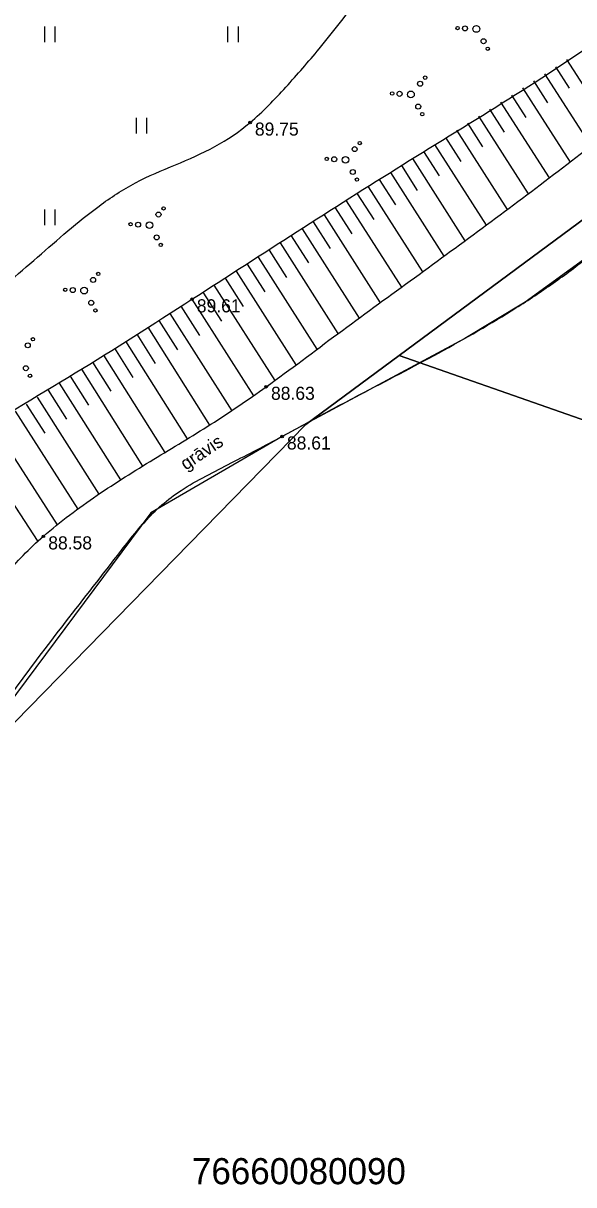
# Model space of a CAD drawing. Extents: x 635228 to 635525, y 248590 to 248800.
# Drawn here: x 635410.17 to 635431.23, y 248638.32 to 248682.72 of the extents above; entities that cross this region are included whole.
import ezdxf

# ---------------------------------------------------------------- set-up
doc = ezdxf.new("R2010")
doc.units = 0
for name, color, linetype in [('HIDG_GRAV_####_####_#', 7, 'Continuous'), ('HIDG_GRAV_####_TKST_#', 7, 'Continuous'), ('RAMI_UZMR_####_####_#', 7, 'Continuous'), ('RELJ_AATZ_####_TKST_#', 7, 'Continuous'), ('RELJ_ELEM_####_####_#', 7, 'Continuous'), ('RELJ_HORZ_RESN_####_#', 7, 'Continuous'), ('RELJ_NOGA_####_####_#', 7, 'Continuous'), ('ROBZ_IERR_####_####_#', 7, 'Continuous'), ('ROBZ_UZMR_####_####_#', 7, 'Continuous'), ('ROBZ_UZMR_####_TKST_#', 7, 'Continuous'), ('TERT_ELEM_####_####_#', 7, 'Continuous'), ('TERT_KONT_####_####_#', 7, 'Continuous')]:
    doc.layers.add(name, color=color, linetype=linetype)

msp = doc.modelspace()

# ---------------------------------------------------------------- linework, layer by layer
at = {"layer": 'HIDG_GRAV_####_####_#'}
for points in [[(635394.244, 248623.295), (635394.9074355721, 248630.6631552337), (635396.5650242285, 248636.944974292), (635397.8888882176, 248639.97580624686), (635399.2686043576, 248642.98780740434), (635400.0423829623, 248644.69884236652), (635400.835233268, 248646.3905777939), (635402.4795660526, 248649.72803076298), (635404.20443685, 248653.0239277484), (635406.0126797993, 248656.30203018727), (635407.0670223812, 248658.14081276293), (635408.1930324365, 248659.92698593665), (635409.4621962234, 248661.60192368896), (635410.172800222, 248662.37935865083), (635410.946, 248663.10700000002), (635413.0008032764, 248664.6744257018), (635415.1640977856, 248666.05372522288), (635417.3478434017, 248667.38916213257), (635419.464, 248668.825), (635422.2083511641, 248670.85354035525), (635424.965867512, 248672.86854694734), (635430.4558647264, 248676.93578902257), (635435.8049295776, 248681.1823865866), (635438.3862804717, 248683.4215875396), (635439.6466024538, 248684.57867623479), (635440.8840000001, 248685.76400000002), (635443.6087249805, 248688.6747140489), (635446.1599310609, 248691.73220612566), (635448.6719216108, 248694.81834513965), (635451.279, 248697.815), (635453.9336502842, 248700.48189136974), (635456.6811388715, 248703.07136968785), (635459.3523080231, 248705.7266631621), (635461.7780000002, 248708.59100000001), (635461.778, 248708.59100000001)], [(635396.7397638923, 248625.2320466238), (635397.9986579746, 248634.27312358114), (635398.9188026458, 248636.96227546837), (635399.5920874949, 248638.24717771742), (635399.9292604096, 248638.88899780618), (635400.2466831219, 248639.53584001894), (635401.591165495, 248642.41958219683), (635402.9524948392, 248645.2868638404), (635405.8217854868, 248650.96088254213), (635407.5583128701, 248653.91205967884), (635409.4799859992, 248656.7354955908), (635411.5283407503, 248659.48290512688), (635413.6449129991, 248662.20600313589), (635414.8182615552, 248663.6538935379), (635415.4704678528, 248664.3057478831), (635416.2076616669, 248664.85985159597), (635417.1601741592, 248665.41138033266), (635418.1313630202, 248665.91742947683), (635419.1067857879, 248666.41122678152), (635420.072, 248666.926), (635421.5645353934, 248667.7418115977), (635423.0692260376, 248668.5354410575), (635426.0762392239, 248670.12612318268), (635429.0153718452, 248671.8379856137), (635430.4352117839, 248672.78309045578), (635431.128452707, 248673.2855892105), (635431.8089561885, 248673.81096758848), (635433.1953696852, 248675.0040709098), (635434.526751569, 248676.2563297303), (635437.0226234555, 248678.92292892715), (635441.762, 248684.467), (635443.1273679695, 248686.0473501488), (635444.4678763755, 248687.6485508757), (635447.1219662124, 248690.87245996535), (635449.819572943, 248694.05663907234), (635451.2144774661, 248695.60817732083), (635452.6560000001, 248697.119), (635458.0231966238, 248702.2419696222), (635463.584, 248707.15000000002)]]:
    msp.add_spline(points, degree=3, dxfattribs=at)
at = {"layer": 'RAMI_UZMR_####_####_#'}
msp.add_lwpolyline([(635426.003, 248728.15499999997), (635436.69, 248722.584), (635450.108, 248715.45700000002), (635458.287, 248711.34600000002), (635461.7780000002, 248708.59100000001), (635463.584, 248707.15000000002), (635452.6560000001, 248697.119), (635441.762, 248684.467), (635435.9528772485, 248677.73413872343), (635432.018527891, 248673.97985762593), (635429.363741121, 248672.06248825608), (635427.0556775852, 248670.66460585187), (635420.072, 248666.926), (635415.05332695, 248664.00973325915), (635408.095218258, 248654.65947737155), (635398.6701763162, 248636.43948679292), (635398.046283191, 248634.41686083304), (635396.3166782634, 248622.87374513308), (635394.244, 248623.295), (635390.206, 248622.483), (635381.566, 248626.41900000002), (635379.918, 248627.738), (635364.657, 248634.36500000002)], dxfattribs=at)
at = {"layer": 'RELJ_ELEM_####_####_#'}
for centre in [(635418.848, 248678.924), (635416.627, 248672.168), (635419.464, 248668.825), (635420.072, 248666.926), (635410.946, 248663.10700000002)]:
    msp.add_circle(centre, 0.05, dxfattribs=at)
at = {"layer": 'RELJ_HORZ_RESN_####_#'}
msp.add_spline([(635396.8403365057, 248673.83023932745), (635398.5699520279, 248674.74721849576), (635400.1196081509, 248675.6687893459), (635401.3847631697, 248676.59316814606), (635401.8779834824, 248677.05585311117), (635402.2608753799, 248677.51857116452), (635402.5005008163, 248677.92779942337), (635402.9962003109, 248679.47940420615), (635403.1093939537, 248680.10527297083), (635403.2077718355, 248680.73304831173), (635403.3050539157, 248681.36081107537), (635403.4149601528, 248681.98664210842), (635403.9947087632, 248684.49620174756), (635404.4941894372, 248685.58182624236), (635404.822447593, 248686.0525951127), (635405.213, 248686.464), (635405.5227683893, 248686.49325254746), (635405.8948771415, 248686.27621660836), (635406.269797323, 248686.04907236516), (635406.588, 248686.048), (635407.1331532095, 248686.47133617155), (635407.6549224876, 248686.94769115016), (635408.6437981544, 248688.02779111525), (635410.511320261, 248690.47588617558), (635412.43838879, 248692.8856225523), (635414.0718482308, 248694.36296271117), (635414.672826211, 248694.7503376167), (635415.8418707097, 248695.38166460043), (635417.0157559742, 248695.99905223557), (635418.2014500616, 248696.5900310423), (635419.4059210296, 248697.14213154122), (635424.3998390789, 248699.29274669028), (635429.4588912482, 248701.50672660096), (635434.3873884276, 248704.0886148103), (635435.2434356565, 248704.60530447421), (635437.7315604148, 248706.27775516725), (635439.1970704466, 248707.5552960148), (635439.8338858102, 248708.26101524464), (635440.1227716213, 248708.63326282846), (635440.3898668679, 248709.01944554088), (635440.6922176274, 248709.6864690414), (635440.8034457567, 248710.32396866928)], degree=3, dxfattribs=at)
at = {"layer": 'RELJ_NOGA_####_####_#'}
for p, q in [((635430.5266066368, 248681.05692283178), (635431.0519157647, 248680.24090699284)), ((635430.9470252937, 248681.3275667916), (635432.6731329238, 248678.64622909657)), ((635430.1061815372, 248680.7862888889), (635431.879304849, 248678.02717532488)), ((635429.2649208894, 248680.2456591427), (635431.084098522, 248677.41488158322)), ((635429.6855512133, 248680.5159740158), (635430.2245122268, 248679.67731004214)), ((635428.423315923, 248679.70556556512), (635430.2842333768, 248676.80569698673)), ((635428.8441217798, 248679.97560710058), (635429.3959754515, 248679.1156532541)), ((635428.0024688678, 248679.43558828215), (635428.5663567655, 248678.5554283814)), ((635427.1604519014, 248678.89613723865), (635427.7363538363, 248677.9972248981)), ((635427.5814603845, 248679.16586276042), (635429.4813910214, 248676.200303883)), ((635426.3183540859, 248678.35681247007), (635426.9051811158, 248677.43969685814)), ((635426.7394434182, 248678.62641171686), (635428.6783507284, 248675.6000150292)), ((635425.8971919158, 248678.08732698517), (635427.8717630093, 248675.0013921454)), ((635425.0547269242, 248677.54857591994), (635427.0641464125, 248674.40564282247)), ((635425.4759878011, 248677.81790707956), (635426.0734693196, 248676.88338621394)), ((635424.6334638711, 248677.2792481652), (635425.2412367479, 248676.32791820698)), ((635423.7907590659, 248676.74087226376), (635424.408884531, 248675.77333768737)), ((635424.2121114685, 248677.0100602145), (635426.2553767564, 248673.8117939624)), ((635422.9479559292, 248676.20265032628), (635423.5759655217, 248675.21902551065)), ((635423.369385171, 248676.4717179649), (635425.4459030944, 248673.21935592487)), ((635422.5265266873, 248675.93358268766), (635424.6367393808, 248672.628445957)), ((635421.683602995, 248675.395549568), (635423.8268924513, 248672.03703705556)), ((635422.1050892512, 248675.6645278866), (635422.7430063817, 248674.66491831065)), ((635420.8406304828, 248674.8575929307), (635423.0178154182, 248671.4459665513)), ((635421.262116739, 248675.12657124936), (635421.9101732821, 248674.11107331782)), ((635420.4191442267, 248674.58861461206), (635421.0774288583, 248673.55708937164)), ((635419.5761717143, 248674.05065797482), (635420.2449094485, 248673.00275282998)), ((635419.9976579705, 248674.31963629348), (635422.2092448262, 248670.8541024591)), ((635418.7331992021, 248673.51270133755), (635419.4126894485, 248672.44794711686)), ((635419.1546854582, 248673.78167965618), (635421.4015228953, 248670.26090852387)), ((635418.311757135, 248673.2436537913), (635420.5957499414, 248669.66631951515)), ((635417.4688977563, 248672.70551991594), (635419.7908028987, 248669.0688049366)), ((635417.8903274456, 248672.9745868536), (635418.5811471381, 248671.89258127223)), ((635416.6260381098, 248672.1673864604), (635418.9818020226, 248668.47408559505)), ((635417.047468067, 248672.4364529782), (635417.7498791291, 248671.336292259)), ((635416.2043934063, 248671.89865673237), (635416.9130730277, 248670.7846281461)), ((635415.3598923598, 248671.36310347), (635416.0682259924, 248670.24203794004)), ((635415.7822665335, 248671.63068518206), (635418.1455230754, 248667.90264789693)), ((635414.5141425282, 248670.8295240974), (635415.2195002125, 248669.7073233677)), ((635414.9371250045, 248671.09614334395), (635417.2947611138, 248667.35588774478)), ((635414.0908198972, 248670.5634452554), (635416.4389943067, 248666.82757749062)), ((635413.2441746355, 248670.03128757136), (635415.5840345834, 248666.30864783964)), ((635413.6674972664, 248670.29736641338), (635414.3707254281, 248669.1785536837)), ((635412.3975310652, 248669.49912719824), (635414.7326200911, 248665.78930868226)), ((635412.8208520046, 248669.76520872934), (635413.521585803, 248668.65036444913)), ((635411.9743774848, 248669.23277959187), (635412.674411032, 248668.12061753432)), ((635411.1286100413, 248668.69922813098), (635411.8312024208, 248667.58616171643)), ((635411.5514225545, 248668.96611683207), (635413.8901244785, 248665.2610801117)), ((635410.2841650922, 248668.1635865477), (635410.9965072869, 248667.04570592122)), ((635410.7061891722, 248668.43172009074), (635413.0645891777, 248664.71781451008)), ((635409.8625812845, 248667.8947613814), (635412.2588250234, 248664.15017364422)), ((635409.0209685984, 248667.3546810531), (635411.471024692, 248663.54545166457)), ((635408.1819740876, 248666.81054345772), (635410.7270639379, 248662.91267369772))]:
    msp.add_line(p, q, dxfattribs=at)
msp.add_spline([(635390.206, 248622.483), (635392.6761559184, 248639.41621940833), (635395.6724652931, 248647.2597307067), (635397.9131924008, 248650.95381667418), (635399.048256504, 248652.79837067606), (635400.128, 248654.662), (635400.9493075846, 248656.2558432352), (635403.3016292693, 248661.16811378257), (635405.1862207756, 248664.14373210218), (635407.706, 248666.499), (635412.1610828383, 248669.3503906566), (635416.627, 248672.168), (635424.6828055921, 248677.31078055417), (635432.728, 248682.47600000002), (635436.7060689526, 248685.70428438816), (635438.5008534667, 248687.5575466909), (635440.2150000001, 248689.48700000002), (635442.5291182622, 248692.3528262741), (635444.7219287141, 248695.30565037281), (635446.9190248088, 248698.24939928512), (635449.246, 248701.08800000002), (635451.3600052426, 248703.48451832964), (635453.4937434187, 248705.86484004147), (635457.9500000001, 248710.44), (635458.6576193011, 248711.10744185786)], degree=3, dxfattribs=at)
at = {"layer": 'ROBZ_IERR_####_####_#'}
msp.add_lwpolyline([(635522.337313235, 248635.85405923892), (635430.9589999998, 248667.77300000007), (635424.5429999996, 248670.01400000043), (635439.4570000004, 248681.03800000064), (635465.4589999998, 248707.53900000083), (635482.5609999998, 248729.82799999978), (635498.1289999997, 248747.85500000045)], dxfattribs=at)
at = {"layer": 'ROBZ_UZMR_####_####_#'}
msp.add_lwpolyline([(635325.5420000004, 248659.74000000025), (635329.6529999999, 248676.3660000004), (635327.79, 248676.82799999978), (635337.4600999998, 248688.65990000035), (635343.3430000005, 248703.1199999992), (635360.483, 248762.61500000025), (635458.6069999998, 248711.13399999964), (635465.4589999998, 248707.53900000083), (635439.4570000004, 248681.03800000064), (635424.5429999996, 248670.01400000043), (635420.9790000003, 248667.37900000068), (635407.0700000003, 248653.17999999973), (635400.0669999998, 248641.1490000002), (635395.1619999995, 248617.53900000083), (635389.0310000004, 248621.06200000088), (635375.858, 248629.11500000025)], close=True, dxfattribs=at)
msp.add_lwpolyline([(635432.3373132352, 248596.18186087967), (635395.1619999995, 248617.53900000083), (635400.0669999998, 248641.1490000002), (635407.0700000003, 248653.17999999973), (635420.9790000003, 248667.37900000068), (635424.5429999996, 248670.01400000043), (635430.9589999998, 248667.77300000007), (635522.3373132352, 248635.85405923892)], dxfattribs=at)
at = {"layer": 'TERT_ELEM_####_####_#'}
for p, q in [((635411, 248682), (635411, 248682.6)), ((635411.4, 248682), (635411.4, 248682.6)), ((635418, 248682), (635418, 248682.6)), ((635418.4, 248682), (635418.4, 248682.6)), ((635414.5, 248678.5), (635414.5, 248679.1)), ((635414.9, 248678.5), (635414.9, 248679.1)), ((635411, 248675), (635411, 248675.6)), ((635411.4, 248675), (635411.4, 248675.6))]:
    msp.add_line(p, q, dxfattribs=at)
for centre, radius in [((635426.7816, 248682.53423999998), 0.06400000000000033), ((635427.06608, 248682.52079999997), 0.09600000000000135), ((635427.5, 248682.5), 0.12800000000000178), ((635427.77648, 248682.03311999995), 0.09600000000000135), ((635427.93392, 248681.74383999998), 0.06400000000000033), ((635425.544, 248680.63935999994), 0.06400000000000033), ((635425.3475200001, 248680.40767999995), 0.09600000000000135), ((635424.2816, 248680.03423999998), 0.06400000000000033), ((635424.56608, 248680.02079999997), 0.09600000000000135), ((635425, 248680), 0.12800000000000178), ((635425.27648, 248679.53311999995), 0.09600000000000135), ((635425.43392, 248679.24383999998), 0.06400000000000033), ((635422.8475200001, 248677.90767999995), 0.09600000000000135), ((635423.044, 248678.13935999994), 0.06400000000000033), ((635421.7816, 248677.53423999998), 0.06400000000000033), ((635422.06608, 248677.52079999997), 0.09600000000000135), ((635422.5, 248677.5), 0.12800000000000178), ((635422.77648, 248677.03311999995), 0.09600000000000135), ((635422.93392, 248676.74383999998), 0.06400000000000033), ((635415.544, 248675.63935999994), 0.06400000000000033), ((635415.3475200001, 248675.40767999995), 0.09600000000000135), ((635414.2816, 248675.03423999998), 0.06400000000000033), ((635414.56608, 248675.02079999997), 0.09600000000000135), ((635415, 248675), 0.12800000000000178), ((635415.27648, 248674.53311999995), 0.09600000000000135), ((635415.43392, 248674.24383999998), 0.06400000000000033), ((635413.044, 248673.13935999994), 0.06400000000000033), ((635411.7816, 248672.53423999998), 0.06400000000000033), ((635412.06608, 248672.52079999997), 0.09600000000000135), ((635412.5, 248672.5), 0.12800000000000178), ((635412.8475200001, 248672.90767999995), 0.09600000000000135), ((635412.77648, 248672.03311999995), 0.09600000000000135), ((635412.93392, 248671.74383999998), 0.06400000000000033), ((635410.3475200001, 248670.40767999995), 0.09600000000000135), ((635410.544, 248670.63935999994), 0.06400000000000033), ((635410.27648, 248669.53311999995), 0.09600000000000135), ((635410.43392, 248669.24383999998), 0.06400000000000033)]:
    msp.add_circle(centre, radius, dxfattribs=at)
at = {"layer": 'TERT_KONT_####_####_#'}
msp.add_spline([(635381.566, 248626.41900000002), (635384.141, 248634.765), (635385.389202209, 248637.7914590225), (635387.0292419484, 248640.6516206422), (635388.8146607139, 248643.4497219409), (635389.6848689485, 248644.8580740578), (635390.4990000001, 248646.29), (635392.0226550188, 248649.21918285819), (635393.5071185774, 248652.1702394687), (635395.0017728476, 248655.12192634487), (635396.556, 248658.053), (635399.9011134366, 248663.08488427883), (635403.9259848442, 248667.61643358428), (635408.395257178, 248671.78623589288), (635410.7229946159, 248673.7787906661), (635413.0735733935, 248675.7328791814), (635414.4692599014, 248676.62068389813), (635415.9938205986, 248677.30794837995), (635417.5018643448, 248678.0054584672), (635418.848, 248678.924), (635420.219040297, 248680.28079949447), (635421.4913245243, 248681.74225536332), (635423.8682567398, 248684.84208090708), (635426.2360605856, 248687.94936599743), (635428.1606833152, 248690.11983046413), (635428.8520000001, 248690.79), (635429.5317929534, 248691.3720486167), (635430.2428233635, 248691.92597447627), (635430.954192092, 248692.47941309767), (635431.635, 248693.06), (635432.7520114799, 248694.18745503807), (635433.7815998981, 248695.39485218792), (635435.7079899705, 248697.94525714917), (635437.6731350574, 248700.50278353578), (635438.7511672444, 248701.71908246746), (635439.936, 248702.85900000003), (635442.1191491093, 248704.47891720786), (635444.4652000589, 248705.76616705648), (635446.9243060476, 248706.83607415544), (635448.1806775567, 248707.32556311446), (635449.4466202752, 248707.80396311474), (635450.5789798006, 248708.1275799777), (635451.7602437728, 248708.30057270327), (635452.9245409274, 248708.35276985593), (635454.0060000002, 248708.314), (635454.3355621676, 248708.1390314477), (635454.6423695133, 248707.79518323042), (635454.9454921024, 248707.47799339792), (635455.2640000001, 248707.383), (635455.8819855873, 248707.57371461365), (635456.5298319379, 248707.8540188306), (635457.157262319, 248708.21606363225), (635457.714, 248708.652), (635459.5420464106, 248710.35555231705)], degree=3, dxfattribs=at)

# ---------------------------------------------------------------- texts
at = {"layer": 'HIDG_GRAV_####_TKST_#'}
msp.add_text('grāvis', height=0.5, rotation=33.910518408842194, dxfattribs=at).set_placement((635416.3931946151, 248665.615577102))
at = {"layer": 'RELJ_AATZ_####_TKST_#'}
for s, p in [(' 89.75', (635418.848, 248678.424)), (' 89.61', (635416.627, 248671.668)), (' 88.63', (635419.464, 248668.325)), (' 88.61', (635420.072, 248666.426)), (' 88.58', (635410.946, 248662.60700000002))]:
    msp.add_text(s, height=0.5, dxfattribs=at).set_placement(p)
at = {"layer": 'ROBZ_UZMR_####_TKST_#'}
msp.add_text('76660080090', height=1, dxfattribs=at).set_placement((635416.6255897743, 248638.34092057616))

doc.saveas('drawing.dxf')
